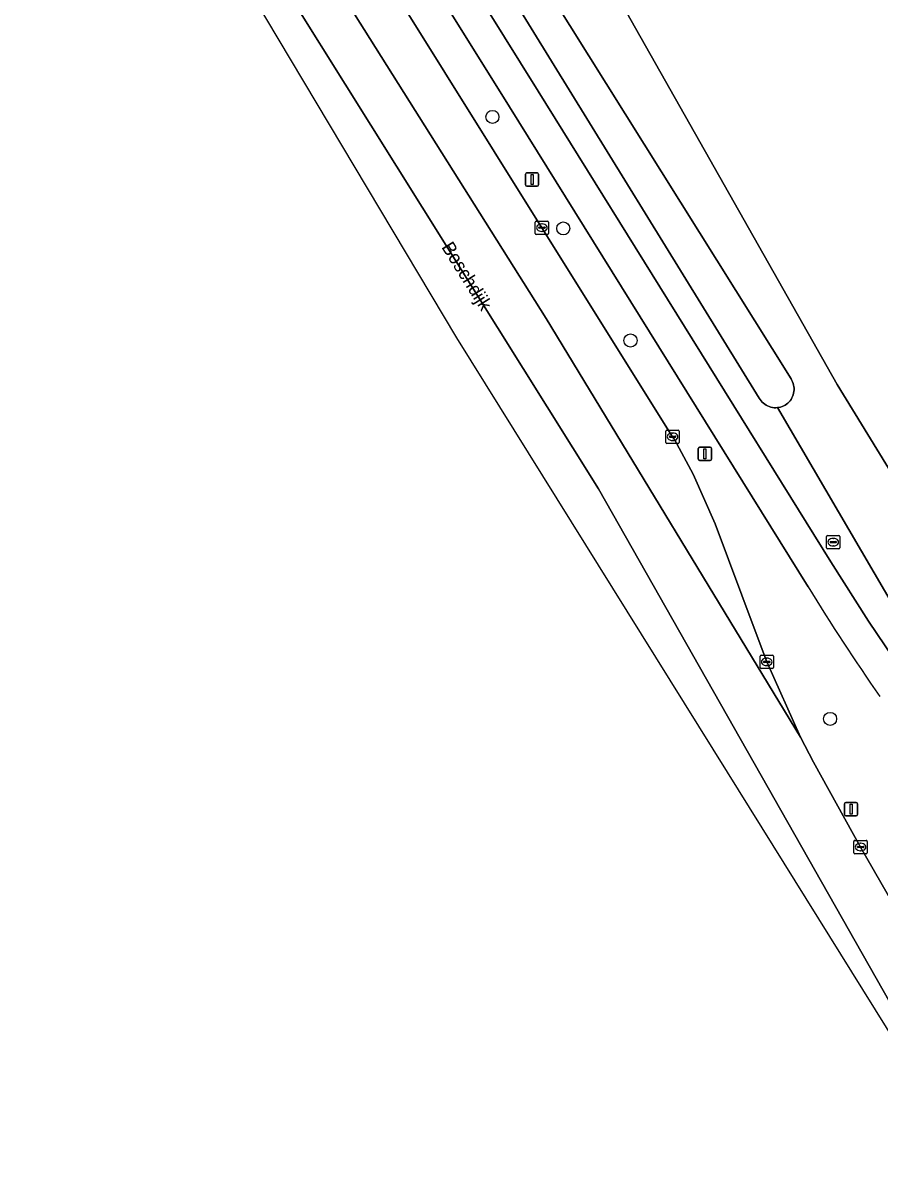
# Model space of a CAD drawing. Extents: x 158835 to 160077, y 386387 to 387778.
# Drawn here: x 159164.1 to 159228.4, y 386574.6 to 386661.2 of the extents above; entities that cross this region are included whole.
import ezdxf

# ---------------------------------------------------------------- set-up
doc = ezdxf.new("R2010")
doc.units = 0
for name, color, linetype in [('IMGEO_Berm_groen', 7, 'Continuous'), ('IMGEO_Boom', 7, 'Continuous'), ('IMGEO_Brandkraan', 7, 'Continuous'), ('IMGEO_Fietspad_gesloten', 7, 'Continuous'), ('IMGEO_Groenvoorziening', 7, 'Continuous'), ('IMGEO_Kolk', 7, 'Continuous'), ('IMGEO_Lichtmast', 7, 'Continuous'), ('IMGEO_Loofbos', 7, 'Continuous'), ('IMGEO_Openbare_ruimte_label', 7, 'Continuous'), ('IMGEO_Rijbaan_regionaal_gesloten', 7, 'Continuous'), ('IMGEO_Waterloop', 7, 'Continuous')]:
    doc.layers.add(name, color=color, linetype=linetype)

msp = doc.modelspace()

# ---------------------------------------------------------------- linework, layer by layer
at = {"layer": 'IMGEO_Berm_groen'}
for points in [[(159178.431, 386695.058), (159202.745, 386656.083), (159224.678, 386620.804), (159227.505, 386616.352), (159231.872, 386609.903), (159233.273, 386610.83), (159220.671, 386632.367), (159220.547, 386632.36), (159220.422, 386632.364), (159220.299, 386632.38), (159220.177, 386632.406), (159220.059, 386632.444), (159219.944, 386632.492), (159219.833, 386632.549), (159219.729, 386632.617), (159219.631, 386632.693), (159219.54, 386632.778), (159219.457, 386632.871), (159219.382, 386632.971), (159219.317, 386633.077), (159182.455, 386692.864)], [(159200.586, 386654.914), (159184.27, 386681.064), (159187.243, 386671.128), (159192.163, 386663.234), (159203.017, 386645.855), (159212.816, 386630.184), (159212.948, 386629.976), (159214.359, 386627.371), (159216.006, 386623.671), (159219.009, 386615.649), (159219.878, 386613.309), (159222.398, 386607.673), (159223.378, 386605.792), (159226.911, 386599.431), (159233.96, 386587.187), (159235.681, 386584.197), (159238.851, 386578.829), (159239.908, 386577.097), (159241.609, 386574.556)], [(159222.974, 386618.927), (159200.586, 386654.914)]]:
    msp.add_lwpolyline(points, dxfattribs=at)
msp.add_arc((159373.542, 386711.746), 176.879, 211.65218, 214.83512, dxfattribs=at)
at = {"layer": 'IMGEO_Boom'}
for centre in [(159199.309, 386654.164), (159204.62, 386645.805), (159209.658, 386637.402), (159224.629, 386609.039)]:
    msp.add_circle(centre, 0.489, dxfattribs=at)
at = {"layer": 'IMGEO_Brandkraan'}
for p, q in [((159224.435, 386622.785), (159225.287, 386622.785)), ((159224.36, 386621.859), (159224.36, 386622.711)), ((159224.619, 386622.279), (159224.619, 386622.291)), ((159225.057, 386622.242), (159224.659, 386622.242)), ((159224.662, 386622.328), (159225.06, 386622.328)), ((159224.871, 386622.005), (159224.846, 386622.005)), ((159224.848, 386622.565), (159224.873, 386622.565)), ((159225.103, 386622.291), (159225.103, 386622.279)), ((159225.361, 386622.711), (159225.361, 386621.859)), ((159225.287, 386621.785), (159224.435, 386621.785))]:
    msp.add_line(p, q, dxfattribs=at)
for points in [[(159224.435, 386622.785), (159225.287, 386622.785)], [(159224.36, 386621.859), (159224.36, 386622.711)], [(159225.361, 386622.711), (159225.361, 386621.859)], [(159225.287, 386621.785), (159224.435, 386621.785)]]:
    msp.add_lwpolyline(points, dxfattribs=at)
for centre, radius, start, end in [((159224.437, 386622.709), 0.0765, 91.55205, 178.44795), ((159224.437, 386622.709), 0.0765, 91.55205, 178.44795), ((159225.285, 386622.709), 0.0765, 1.55205, 88.44795), ((159225.285, 386622.709), 0.0765, 1.55205, 88.44795), ((159224.659, 386622.288), 0.0403, 85.87752, 175.75265), ((159224.656, 386622.278), 0.0366, 178.93798, 274.71019), ((159225.06, 386622.285), 0.043, 264.86636, 352.45326), ((159225.064, 386622.29), 0.0386, 1.73085, 96.63898), ((159224.437, 386621.861), 0.0765, 181.55205, 268.44795), ((159224.437, 386621.861), 0.0765, 181.55205, 268.44795), ((159225.285, 386621.861), 0.0765, 271.55205, 358.44795), ((159225.285, 386621.861), 0.0765, 271.55205, 358.44795)]:
    msp.add_arc(centre, radius, start, end, dxfattribs=at)
for centre, major_axis, ratio, start_param, end_param in [((159224.847, 386622.285), (-0.387, 0.002), 0.722429, 4.712389, 7.853982), ((159224.872, 386622.285), (-0.39, 0.002), 0.717154, 1.570796, 4.712389)]:
    msp.add_ellipse(centre, major_axis=major_axis, ratio=ratio, start_param=start_param, end_param=end_param, dxfattribs=at)
at = {"layer": 'IMGEO_Fietspad_gesloten'}
for points in [[(159173.757, 386697.916), (159174.8, 386696.246), (159176.517, 386693.357), (159177.082, 386692.503), (159177.375, 386692.114), (159184.27, 386681.064), (159200.586, 386654.914), (159222.974, 386618.927)], [(159231.872, 386609.903), (159227.505, 386616.352), (159224.678, 386620.804), (159202.745, 386656.083), (159178.431, 386695.058)]]:
    msp.add_lwpolyline(points, dxfattribs=at)
msp.add_arc((159373.542, 386711.746), 176.879, 211.65218, 214.83512, dxfattribs=at)
at = {"layer": 'IMGEO_Groenvoorziening'}
msp.add_lwpolyline([(159189.433, 386697.216), (159213.546, 386714.892), (159236.72, 386731.556), (159235.967, 386725.737), (159223.312, 386713.763), (159221.602, 386693.237), (159222.115, 386690.414), (159249.819, 386639.784), (159265.309, 386620.118), (159242.054, 386606.568), (159225.166, 386634.107)], close=True, dxfattribs=at)
msp.add_lwpolyline([(159184.376, 386694.154), (159221.695, 386634.521), (159221.759, 386634.414), (159221.814, 386634.302), (159221.858, 386634.185), (159221.891, 386634.065), (159221.914, 386633.943), (159221.925, 386633.819), (159221.925, 386633.694), (159221.915, 386633.57), (159221.893, 386633.448), (159221.86, 386633.328), (159221.817, 386633.211), (159221.764, 386633.099), (159221.701, 386632.991), (159221.628, 386632.89), (159221.547, 386632.796), (159221.457, 386632.709), (159221.36, 386632.631), (159221.257, 386632.562), (159221.148, 386632.502), (159221.034, 386632.452), (159220.915, 386632.413), (159220.794, 386632.384), (159220.671, 386632.367), (159233.273, 386610.83)], dxfattribs=at)
at = {"layer": 'IMGEO_Kolk'}
for p, q in [((159202.517, 386645.429), (159202.517, 386646.281)), ((159202.592, 386646.355), (159203.444, 386646.355)), ((159203.518, 386646.281), (159203.518, 386645.429)), ((159203.444, 386645.355), (159202.592, 386645.355)), ((159202.776, 386645.849), (159202.776, 386645.861)), ((159203.214, 386645.812), (159202.816, 386645.812)), ((159202.819, 386645.898), (159203.217, 386645.898)), ((159203.028, 386645.575), (159203.003, 386645.575)), ((159203.005, 386646.135), (159203.03, 386646.135)), ((159203.26, 386645.861), (159203.26, 386645.849)), ((159212.316, 386629.759), (159212.316, 386630.611)), ((159212.391, 386630.685), (159213.243, 386630.685)), ((159213.317, 386630.611), (159213.317, 386629.759)), ((159213.243, 386629.685), (159212.391, 386629.685)), ((159212.575, 386630.179), (159212.575, 386630.191)), ((159213.013, 386630.142), (159212.615, 386630.142)), ((159212.618, 386630.228), (159213.016, 386630.228)), ((159212.827, 386629.905), (159212.802, 386629.905)), ((159212.804, 386630.465), (159212.829, 386630.465)), ((159213.059, 386630.191), (159213.059, 386630.179)), ((159219.379, 386612.884), (159219.379, 386613.736)), ((159219.454, 386613.81), (159220.306, 386613.81)), ((159219.638, 386613.304), (159219.638, 386613.316)), ((159220.076, 386613.267), (159219.678, 386613.267)), ((159219.681, 386613.353), (159220.079, 386613.353)), ((159219.867, 386613.59), (159219.892, 386613.59)), ((159220.122, 386613.316), (159220.122, 386613.304)), ((159220.38, 386613.736), (159220.38, 386612.884)), ((159220.306, 386612.81), (159219.454, 386612.81)), ((159219.89, 386613.03), (159219.865, 386613.03)), ((159226.412, 386599.006), (159226.412, 386599.858)), ((159226.487, 386599.932), (159227.339, 386599.932)), ((159226.671, 386599.426), (159226.671, 386599.438)), ((159227.109, 386599.389), (159226.711, 386599.389)), ((159226.714, 386599.475), (159227.112, 386599.475)), ((159226.9, 386599.712), (159226.925, 386599.712)), ((159227.155, 386599.438), (159227.155, 386599.426)), ((159227.413, 386599.858), (159227.413, 386599.006)), ((159227.339, 386598.932), (159226.487, 386598.932)), ((159226.923, 386599.152), (159226.898, 386599.152))]:
    msp.add_line(p, q, dxfattribs=at)
for points in [[(159202.517, 386645.429), (159202.517, 386646.281)], [(159202.592, 386646.355), (159203.444, 386646.355)], [(159203.518, 386646.281), (159203.518, 386645.429)], [(159203.444, 386645.355), (159202.592, 386645.355)], [(159212.316, 386629.759), (159212.316, 386630.611)], [(159212.391, 386630.685), (159213.243, 386630.685)], [(159213.317, 386630.611), (159213.317, 386629.759)], [(159213.243, 386629.685), (159212.391, 386629.685)], [(159219.379, 386612.884), (159219.379, 386613.736)], [(159219.454, 386613.81), (159220.306, 386613.81)], [(159220.38, 386613.736), (159220.38, 386612.884)], [(159220.306, 386612.81), (159219.454, 386612.81)], [(159226.412, 386599.006), (159226.412, 386599.858)], [(159226.487, 386599.932), (159227.339, 386599.932)], [(159227.413, 386599.858), (159227.413, 386599.006)], [(159227.339, 386598.932), (159226.487, 386598.932)]]:
    msp.add_lwpolyline(points, dxfattribs=at)
for centre, radius, start, end in [((159202.594, 386646.279), 0.0765, 91.55205, 178.44795), ((159202.594, 386646.279), 0.0765, 91.55205, 178.44795), ((159203.442, 386646.279), 0.0765, 1.55205, 88.44795), ((159203.442, 386646.279), 0.0765, 1.55205, 88.44795), ((159202.594, 386645.431), 0.0765, 181.55205, 268.44795), ((159202.594, 386645.431), 0.0765, 181.55205, 268.44795), ((159202.816, 386645.858), 0.0403, 85.87752, 175.75265), ((159202.813, 386645.848), 0.0366, 178.93798, 274.71019), ((159203.217, 386645.855), 0.043, 264.86636, 352.45326), ((159203.221, 386645.86), 0.0386, 1.73085, 96.63898), ((159203.442, 386645.431), 0.0765, 271.55205, 358.44795), ((159203.442, 386645.431), 0.0765, 271.55205, 358.44795), ((159212.393, 386630.609), 0.0765, 91.55205, 178.44795), ((159212.393, 386630.609), 0.0765, 91.55205, 178.44795), ((159213.241, 386630.609), 0.0765, 1.55205, 88.44795), ((159213.241, 386630.609), 0.0765, 1.55205, 88.44795), ((159212.393, 386629.761), 0.0765, 181.55205, 268.44795), ((159212.393, 386629.761), 0.0765, 181.55205, 268.44795), ((159212.615, 386630.188), 0.0403, 85.87752, 175.75265), ((159212.612, 386630.178), 0.0366, 178.93798, 274.71019), ((159213.016, 386630.185), 0.043, 264.86636, 352.45326), ((159213.02, 386630.19), 0.0386, 1.73085, 96.63898), ((159213.241, 386629.761), 0.0765, 271.55205, 358.44795), ((159213.241, 386629.761), 0.0765, 271.55205, 358.44795), ((159219.456, 386613.734), 0.0765, 91.55205, 178.44795), ((159219.456, 386613.734), 0.0765, 91.55205, 178.44795), ((159219.678, 386613.313), 0.0403, 85.87752, 175.75265), ((159219.675, 386613.303), 0.0366, 178.93798, 274.71019), ((159220.079, 386613.31), 0.043, 264.86636, 352.45326), ((159220.083, 386613.315), 0.0386, 1.73085, 96.63898), ((159220.304, 386613.734), 0.0765, 1.55205, 88.44795), ((159220.304, 386613.734), 0.0765, 1.55205, 88.44795), ((159219.456, 386612.886), 0.0765, 181.55205, 268.44795), ((159219.456, 386612.886), 0.0765, 181.55205, 268.44795), ((159220.304, 386612.886), 0.0765, 271.55205, 358.44795), ((159220.304, 386612.886), 0.0765, 271.55205, 358.44795), ((159226.489, 386599.856), 0.0765, 91.55205, 178.44795), ((159226.489, 386599.856), 0.0765, 91.55205, 178.44795), ((159226.711, 386599.435), 0.0403, 85.87752, 175.75265), ((159226.708, 386599.425), 0.0366, 178.93798, 274.71019), ((159227.112, 386599.432), 0.043, 264.86636, 352.45326), ((159227.116, 386599.437), 0.0386, 1.73085, 96.63898), ((159227.337, 386599.856), 0.0765, 1.55205, 88.44795), ((159227.337, 386599.856), 0.0765, 1.55205, 88.44795), ((159226.489, 386599.008), 0.0765, 181.55205, 268.44795), ((159226.489, 386599.008), 0.0765, 181.55205, 268.44795), ((159227.337, 386599.008), 0.0765, 271.55205, 358.44795), ((159227.337, 386599.008), 0.0765, 271.55205, 358.44795)]:
    msp.add_arc(centre, radius, start, end, dxfattribs=at)
for centre, major_axis, ratio, start_param, end_param in [((159203.004, 386645.855), (-0.387, 0.002), 0.722429, 4.712389, 7.853982), ((159203.029, 386645.855), (-0.39, 0.002), 0.717154, 1.570796, 4.712389), ((159212.803, 386630.185), (-0.387, 0.002), 0.722429, 4.712389, 7.853982), ((159212.828, 386630.185), (-0.39, 0.002), 0.717154, 1.570796, 4.712389), ((159219.866, 386613.31), (-0.387, 0.002), 0.722429, 4.712389, 7.853982), ((159219.891, 386613.31), (-0.39, 0.002), 0.717154, 1.570796, 4.712389), ((159226.899, 386599.432), (-0.387, 0.002), 0.722429, 4.712389, 7.853982), ((159226.924, 386599.432), (-0.39, 0.002), 0.717154, 1.570796, 4.712389)]:
    msp.add_ellipse(centre, major_axis=major_axis, ratio=ratio, start_param=start_param, end_param=end_param, dxfattribs=at)
at = {"layer": 'IMGEO_Lichtmast'}
for p, q in [((159201.782, 386649.058), (159201.782, 386649.858)), ((159201.782, 386649.858), (159201.782, 386649.058)), ((159201.882, 386649.958), (159202.672, 386649.958)), ((159202.672, 386649.958), (159201.882, 386649.958)), ((159202.772, 386649.858), (159202.772, 386649.058)), ((159202.772, 386649.058), (159202.772, 386649.858)), ((159202.672, 386648.958), (159201.882, 386648.958)), ((159201.882, 386648.958), (159202.672, 386648.958)), ((159214.742, 386628.512), (159214.742, 386629.312)), ((159214.742, 386629.312), (159214.742, 386628.512)), ((159214.842, 386629.412), (159215.632, 386629.412)), ((159215.632, 386629.412), (159214.842, 386629.412)), ((159215.732, 386629.312), (159215.732, 386628.512)), ((159215.732, 386628.512), (159215.732, 386629.312)), ((159215.632, 386628.412), (159214.842, 386628.412)), ((159214.842, 386628.412), (159215.632, 386628.412)), ((159225.702, 386601.876), (159225.702, 386602.676)), ((159225.702, 386602.676), (159225.702, 386601.876)), ((159225.802, 386602.776), (159226.592, 386602.776)), ((159226.592, 386602.776), (159225.802, 386602.776)), ((159226.692, 386602.676), (159226.692, 386601.876)), ((159226.692, 386601.876), (159226.692, 386602.676)), ((159226.592, 386601.776), (159225.802, 386601.776)), ((159225.802, 386601.776), (159226.592, 386601.776))]:
    msp.add_line(p, q, dxfattribs=at)
for points in [[(159202.202, 386649.833), (159202.352, 386649.833), (159202.352, 386649.083), (159202.202, 386649.083), (159202.202, 386649.833)], [(159215.162, 386629.287), (159215.312, 386629.287), (159215.312, 386628.537), (159215.162, 386628.537), (159215.162, 386629.287)], [(159226.122, 386602.651), (159226.272, 386602.651), (159226.272, 386601.901), (159226.122, 386601.901), (159226.122, 386602.651)]]:
    msp.add_lwpolyline(points, dxfattribs=at)
for centre, start, end in [((159201.882, 386649.858), 90, 180), ((159201.882, 386649.858), 90, 180), ((159202.672, 386649.858), 0, 90), ((159202.672, 386649.858), 360, 90), ((159201.882, 386649.058), 180, 270), ((159201.882, 386649.058), 180, 270), ((159202.672, 386649.058), 270, 0), ((159202.672, 386649.058), 270, 0), ((159214.842, 386629.312), 90, 180), ((159214.842, 386629.312), 90, 180), ((159215.632, 386629.312), 0, 90), ((159215.632, 386629.312), 360, 90), ((159214.842, 386628.512), 180, 270), ((159214.842, 386628.512), 180, 270), ((159215.632, 386628.512), 270, 0), ((159215.632, 386628.512), 270, 0), ((159225.802, 386602.676), 90, 180), ((159225.802, 386602.676), 90, 180), ((159226.592, 386602.676), 0, 90), ((159226.592, 386602.676), 360, 90), ((159225.802, 386601.876), 180, 270), ((159225.802, 386601.876), 180, 270), ((159226.592, 386601.876), 270, 0), ((159226.592, 386601.876), 270, 0)]:
    msp.add_arc(centre, 0.1, start, end, dxfattribs=at)
at = {"layer": 'IMGEO_Loofbos'}
msp.add_lwpolyline([(159222.115, 386690.414), (159221.602, 386693.237), (159223.312, 386713.763), (159235.967, 386725.737), (159236.72, 386731.556), (159213.546, 386714.892), (159189.433, 386697.216), (159225.166, 386634.107), (159242.054, 386606.568), (159265.309, 386620.118), (159249.819, 386639.784)], close=True, dxfattribs=at)
at = {"layer": 'IMGEO_Rijbaan_regionaal_gesloten'}
for points in [[(159174.25, 386691.957), (159172.48, 386694.785), (159171.556, 386696.275), (159171.419, 386696.502), (159168.342, 386694.627), (159203.343, 386639.039), (159222.398, 386607.673), (159219.878, 386613.309), (159219.009, 386615.649), (159216.006, 386623.671), (159214.359, 386627.371), (159212.948, 386629.976), (159212.816, 386630.184), (159203.017, 386645.855), (159192.163, 386663.234), (159187.243, 386671.128), (159181.86, 386679.766)], [(159168.342, 386694.627), (159165.539, 386692.92), (159207.253, 386626.278), (159230.609, 386585.166), (159233.96, 386587.187), (159226.911, 386599.431), (159223.378, 386605.792), (159222.398, 386607.673), (159203.343, 386639.039)], [(159229.657, 386584.591), (159230.609, 386585.166), (159207.253, 386626.278), (159165.539, 386692.92), (159164.668, 386692.389), (159164.114, 386692.051), (159196.624, 386637.589), (159216.91, 386605.043)]]:
    msp.add_lwpolyline(points, close=True, dxfattribs=at)
at = {"layer": 'IMGEO_Waterloop'}
msp.add_lwpolyline([(159182.455, 386692.864), (159219.317, 386633.077), (159219.382, 386632.971), (159219.457, 386632.871), (159219.54, 386632.778), (159219.631, 386632.693), (159219.729, 386632.617), (159219.833, 386632.549), (159219.944, 386632.492), (159220.059, 386632.444), (159220.177, 386632.406), (159220.299, 386632.38), (159220.422, 386632.364), (159220.547, 386632.36), (159220.671, 386632.367), (159220.794, 386632.384), (159220.915, 386632.413), (159221.034, 386632.452), (159221.148, 386632.502), (159221.257, 386632.562), (159221.36, 386632.631), (159221.457, 386632.709), (159221.547, 386632.796), (159221.628, 386632.89), (159221.701, 386632.991), (159221.764, 386633.099), (159221.817, 386633.211), (159221.86, 386633.328), (159221.893, 386633.448), (159221.915, 386633.57), (159221.925, 386633.694), (159221.925, 386633.819), (159221.914, 386633.943), (159221.891, 386634.065), (159221.858, 386634.185), (159221.814, 386634.302), (159221.759, 386634.414), (159221.695, 386634.521), (159184.376, 386694.154)], dxfattribs=at)

# ---------------------------------------------------------------- texts
at = {"layer": 'IMGEO_Openbare_ruimte_label'}
msp.add_text('Boschdijk', height=1, rotation=302.00538, dxfattribs=at).set_placement((159195.455, 386644.401))

doc.saveas('drawing.dxf')
